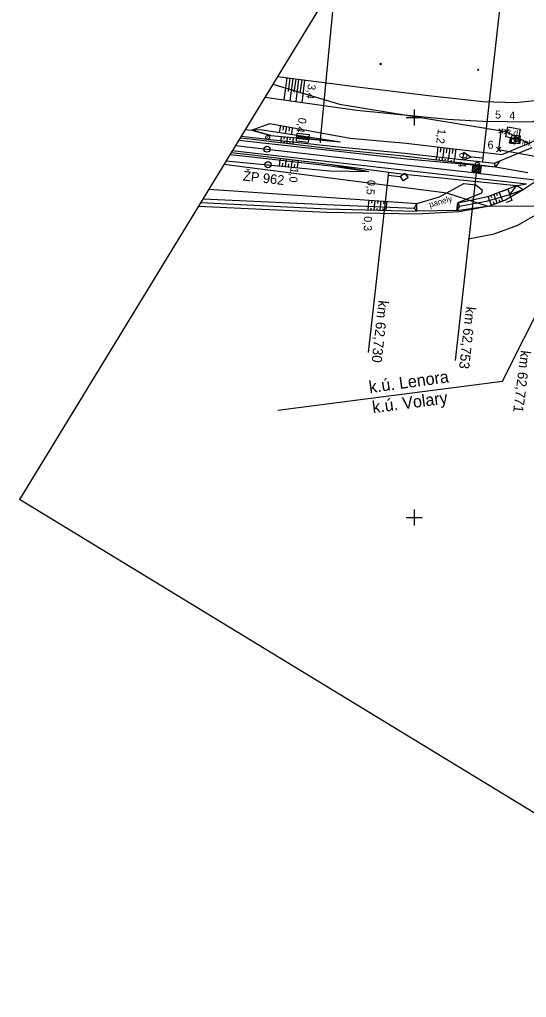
# Model space of a CAD drawing. Extents: x -804899 to -803847, y -1165742 to -1164942.
# Drawn here: x -804898.6 to -804772, y -1165320 to -1165075.5 of the extents above; entities that cross this region are included whole.
import ezdxf

# ---------------------------------------------------------------- set-up
doc = ezdxf.new("R2010")
doc.units = 0
for name, color, linetype in [('0381KM061-064P - Vrstva 1', 7, 'Continuous'), ('0381KM061-064P - Vrstva 16', 7, 'Continuous'), ('0381KM061-064P - Vrstva 23', 7, 'Continuous'), ('0381KM061-064P - Vrstva 27', 7, 'Continuous'), ('0381KM061-064P - Vrstva 3', 7, 'Continuous'), ('0381KM061-064P - Vrstva 33', 7, 'Continuous'), ('0381KM061-064P - Vrstva 4', 7, 'Continuous'), ('0381KM061-064P - Vrstva 43', 7, 'Continuous'), ('0381KM061-064P - Vrstva 48', 7, 'Continuous'), ('0381KM061-064P - Vrstva 49', 7, 'Continuous'), ('0381KM061-064P - Vrstva 51', 7, 'Continuous'), ('0381KM061-064P - Vrstva 55', 7, 'Continuous'), ('0381KM061-064P - Vrstva 7', 7, 'Continuous'), ('0381KM061-064P - Vrstva 8', 7, 'Continuous'), ('Default', 7, 'Continuous'), ('formát', 7, 'Continuous'), ('hran DP - hran DP', 7, 'Continuous'), ('krizky_1000 - Vrstva 1', 7, 'Continuous'), ('PSR_C2_3_Lomove_body_Lenora - Vrstva 60', 7, 'Continuous'), ('PSR_C2_3_trasa_Lenora - Kabelová trasa', 7, 'Continuous'), ('vyt_sit - stávající', 7, 'Continuous')]:
    doc.layers.add(name, color=color, linetype=linetype)

msp = doc.modelspace()

# ---------------------------------------------------------------- linework, layer by layer
at = {"layer": '0381KM061-064P - Vrstva 1'}
for points in [[(-804844.65, -1165107.07), (-804836.78, -1165107.96), (-804807.43, -1165111.28), (-804784.52, -1165113.87), (-804783.45, -1165113.99)], [(-804783.45, -1165113.99), (-804769.78, -1165115.58), (-804758.24, -1165117.11), (-804750.67, -1165118.27), (-804748.02, -1165118.72)]]:
    msp.add_lwpolyline(points, dxfattribs=at)
at = {"layer": '0381KM061-064P - Vrstva 16'}
for p, q in [((-804776.21, -1165106.34), (-804776.22, -1165106.34)), ((-804775.98, -1165105.22), (-804775.98, -1165105.22)), ((-804774.64, -1165105.59), (-804774.63, -1165105.59))]:
    msp.add_line(p, q, dxfattribs=at)
for points in [[(-804774.8, -1165106.64), (-804776.22, -1165106.34), (-804775.98, -1165105.22), (-804774.63, -1165105.59), (-804774.8, -1165106.64)], [(-804774.81, -1165106.64), (-804774.64, -1165105.59), (-804775.98, -1165105.22), (-804776.21, -1165106.34), (-804774.81, -1165106.64), (-804774.8, -1165106.64)], [(-804799.35, -1165123.41), (-804799.3, -1165121.51), (-804793.65, -1165119.83), (-804787.56, -1165116.52), (-804784.63, -1165116.88), (-804783.05, -1165118.1), (-804783.21, -1165118.97), (-804789.08, -1165121.4), (-804789.37, -1165123.31), (-804799.35, -1165123.41)]]:
    msp.add_lwpolyline(points, dxfattribs=at)
at = {"layer": '0381KM061-064P - Vrstva 23'}
msp.add_lwpolyline([(-804776.62, -1165102.34), (-804773.5, -1165102.91), (-804774.04, -1165105.5), (-804777.07, -1165104.85), (-804776.62, -1165102.34)], dxfattribs=at)
at = {"layer": '0381KM061-064P - Vrstva 27'}
for p, q in [((-804774.53, -1165105.54), (-804774.43, -1165105.56)), ((-804784.28, -1165111.73), (-804784.18, -1165111.73))]:
    msp.add_line(p, q, dxfattribs=at)
for centre in [(-804774.48, -1165105.55), (-804784.23, -1165111.73)]:
    msp.add_circle(centre, 0.5, dxfattribs=at)
at = {"layer": '0381KM061-064P - Vrstva 3'}
for p, q in [((-804784.52, -1165113.87), (-804789.79, -1165160.75)), ((-804783.3, -1165111.99), (-804785.51, -1165113.76)), ((-804783.83, -1165111.94), (-804785.45, -1165113.23)), ((-804784.36, -1165111.88), (-804785.4, -1165112.7)), ((-804784.88, -1165111.82), (-804785.34, -1165112.18)), ((-804783.36, -1165112.52), (-804784.99, -1165113.82)), ((-804783.42, -1165113.05), (-804784.46, -1165113.88)), ((-804783.48, -1165113.58), (-804783.93, -1165113.94))]:
    msp.add_line(p, q, dxfattribs=at)
msp.add_lwpolyline([(-804783.53, -1165113.98), (-804785.51, -1165113.76), (-804785.29, -1165111.77), (-804783.3, -1165111.99)], close=True, dxfattribs=at)
at = {"layer": '0381KM061-064P - Vrstva 33'}
for p, q in [((-804775.08, -1165104.96), (-804774.09, -1165105.07)), ((-804774.58, -1165105.01), (-804774.7, -1165106.01))]:
    msp.add_line(p, q, dxfattribs=at)
msp.add_lwpolyline([(-804775.52, -1165104.4), (-804773.53, -1165104.63), (-804773.76, -1165106.62), (-804775.75, -1165106.39), (-804775.52, -1165104.4)], dxfattribs=at)
at = {"layer": '0381KM061-064P - Vrstva 4'}
for points in [[(-804843.83, -1165105.73), (-804840.8, -1165106.06), (-804819.65, -1165108.38), (-804802.7, -1165110.3), (-804779.71, -1165112.39), (-804771.59, -1165113.78)], [(-804843.45, -1165105.1), (-804840.34, -1165105.46), (-804819.52, -1165107.92), (-804802.69, -1165109.64), (-804779.71, -1165112.39)], [(-804845.7, -1165108.79), (-804841.9, -1165109.22), (-804820.58, -1165111.74), (-804803.21, -1165114.08), (-804774.36, -1165117.01), (-804771.98, -1165116.64)], [(-804845.41, -1165108.32), (-804841.86, -1165108.69), (-804820.53, -1165111.13), (-804802.92, -1165113.13), (-804771.98, -1165116.64)]]:
    msp.add_lwpolyline(points, dxfattribs=at)
at = {"layer": '0381KM061-064P - Vrstva 43'}
msp.add_lwpolyline([(-804778.05, -1165118.46), (-804776.64, -1165117.94), (-804775.59, -1165120.75), (-804777, -1165121.27)], dxfattribs=at)
at = {"layer": '0381KM061-064P - Vrstva 48'}
for p, q in [((-804832.45, -1165095.65), (-804831.74, -1165090.13)), ((-804831.42, -1165093.54), (-804831, -1165090.23)), ((-804830.97, -1165095.86), (-804830.25, -1165090.32)), ((-804829.94, -1165093.74), (-804829.51, -1165090.42)), ((-804829.48, -1165096.06), (-804828.77, -1165090.52)), ((-804828.45, -1165093.95), (-804828.02, -1165090.61)), ((-804827.99, -1165096.27), (-804827.28, -1165090.71)), ((-804833.61, -1165103.81), (-804833.29, -1165102.02)), ((-804832.74, -1165103.22), (-804832.55, -1165102.15)), ((-804832.13, -1165104.04), (-804831.81, -1165102.29)), ((-804831.26, -1165103.46), (-804831.07, -1165102.42)), ((-804830.65, -1165104.27), (-804830.33, -1165102.56)), ((-804833.23, -1165105.8), (-804833.29, -1165106.29)), ((-804833.24, -1165105.79), (-804833.15, -1165104.77)), ((-804832.51, -1165106.08), (-804832.54, -1165106.38)), ((-804832.46, -1165105.46), (-804832.4, -1165104.84)), ((-804831.74, -1165105.96), (-804831.8, -1165106.47)), ((-804831.75, -1165105.96), (-804831.66, -1165104.91)), ((-804831.02, -1165106.25), (-804831.05, -1165106.55)), ((-804830.97, -1165105.61), (-804830.91, -1165104.98)), ((-804830.25, -1165106.12), (-804830.31, -1165106.64)), ((-804830.26, -1165106.12), (-804830.16, -1165105.05)), ((-804794.08, -1165107.35), (-804794.37, -1165109.84)), ((-804793.33, -1165107.44), (-804793.48, -1165108.68)), ((-804792.59, -1165107.53), (-804792.88, -1165110.01)), ((-804791.84, -1165107.62), (-804791.99, -1165108.86)), ((-804791.1, -1165107.71), (-804791.39, -1165110.18)), ((-804790.35, -1165107.79), (-804790.5, -1165109.03)), ((-804789.61, -1165107.88), (-804789.9, -1165110.35)), ((-804833.61, -1165112.12), (-804833.46, -1165110.65)), ((-804833.4, -1165110.23), (-804833.45, -1165110.65)), ((-804832.86, -1165112.2), (-804832.79, -1165111.47)), ((-804832.66, -1165110.31), (-804832.68, -1165110.53)), ((-804832.11, -1165112.27), (-804831.97, -1165110.82)), ((-804831.91, -1165110.4), (-804831.96, -1165110.82)), ((-804831.17, -1165110.49), (-804831.19, -1165110.7)), ((-804830.62, -1165112.41), (-804830.48, -1165111)), ((-804830.42, -1165110.58), (-804830.47, -1165111)), ((-804829.68, -1165110.67), (-804829.7, -1165110.87)), ((-804829.13, -1165112.56), (-804828.99, -1165111.17)), ((-804828.93, -1165110.75), (-804828.98, -1165111.17)), ((-804794.47, -1165110.62), (-804794.37, -1165109.84)), ((-804793.72, -1165110.71), (-804793.67, -1165110.32)), ((-804792.98, -1165110.8), (-804792.88, -1165110.01)), ((-804792.23, -1165110.89), (-804792.18, -1165110.49)), ((-804791.49, -1165110.98), (-804791.39, -1165110.18)), ((-804790.74, -1165111.07), (-804790.69, -1165110.67)), ((-804790, -1165111.16), (-804789.9, -1165110.35)), ((-804831.37, -1165112.34), (-804831.3, -1165111.62)), ((-804829.87, -1165112.48), (-804829.81, -1165111.78)), ((-804779.17, -1165119.64), (-804779.44, -1165118.91)), ((-804778.26, -1165119.92), (-804778.74, -1165118.65)), ((-804811.36, -1165120.67), (-804811.46, -1165122.21)), ((-804810.61, -1165120.72), (-804810.66, -1165121.48)), ((-804809.86, -1165120.78), (-804809.96, -1165122.27)), ((-804809.11, -1165120.83), (-804809.16, -1165121.56)), ((-804808.36, -1165120.88), (-804808.46, -1165122.33)), ((-804807.62, -1165120.93), (-804807.67, -1165121.65)), ((-804806.87, -1165120.98), (-804806.97, -1165122.39)), ((-804781.15, -1165120.77), (-804781.55, -1165119.71)), ((-804781.16, -1165120.78), (-804780.73, -1165121.92)), ((-804780.59, -1165120.11), (-804780.84, -1165119.44)), ((-804780.27, -1165121), (-804780.03, -1165121.66)), ((-804779.71, -1165120.34), (-804780.14, -1165119.18)), ((-804779.71, -1165120.35), (-804779.33, -1165121.4)), ((-804778.85, -1165120.54), (-804778.62, -1165121.14)), ((-804778.28, -1165119.92), (-804777.92, -1165120.88)), ((-804811.47, -1165123.14), (-804811.45, -1165122.21)), ((-804810.72, -1165123.15), (-804810.71, -1165122.7)), ((-804809.97, -1165123.17), (-804809.95, -1165122.27)), ((-804809.22, -1165123.19), (-804809.21, -1165122.74)), ((-804808.47, -1165123.2), (-804808.45, -1165122.33)), ((-804807.72, -1165123.22), (-804807.71, -1165122.79)), ((-804806.97, -1165123.24), (-804806.95, -1165122.39))]:
    msp.add_line(p, q, dxfattribs=at)
at = {"layer": '0381KM061-064P - Vrstva 49'}
for p, q in [((-804808.18, -1165086.83), (-804808.54, -1165086.48)), ((-804808.18, -1165086.48), (-804808.54, -1165086.83)), ((-804783.82, -1165088.3), (-804784.18, -1165087.95)), ((-804783.82, -1165087.95), (-804784.18, -1165088.3))]:
    msp.add_line(p, q, dxfattribs=at)
for points in [[(-804782.93, -1165100.95), (-804770.45, -1165101.13), (-804760.77, -1165096.17), (-804750.38, -1165086.38), (-804747.77, -1165080.29)], [(-804834.14, -1165089.82), (-804812.85, -1165092.56), (-804796.39, -1165094.52), (-804782.73, -1165096.03), (-804774.67, -1165096.28), (-804769.92, -1165095.77)], [(-804837.28, -1165094.97), (-804814.35, -1165098.18)], [(-804778.12, -1165109.25), (-804771.87, -1165106.67), (-804764.3, -1165103.24), (-804757.01, -1165099.37), (-804754.14, -1165096.35)], [(-804814.35, -1165098.18), (-804791.62, -1165100.43), (-804782.93, -1165100.95)], [(-804840.64, -1165103.22), (-804836.05, -1165101.51), (-804816.03, -1165105.18), (-804802.02, -1165106.41), (-804778.12, -1165109.25)], [(-804842.2, -1165103.05), (-804840.64, -1165103.22)], [(-804840.64, -1165103.22), (-804838.47, -1165103.07), (-804818.4, -1165106.14)], [(-804840.64, -1165103.22), (-804835.82, -1165104.53), (-804840.64, -1165103.22), (-804835.82, -1165104.53), (-804818.4, -1165106.14)], [(-804843.45, -1165105.1), (-804840.34, -1165105.46), (-804819.52, -1165107.92), (-804802.69, -1165109.64), (-804779.71, -1165112.39)], [(-804843.18, -1165104.66), (-804835.93, -1165105.5), (-804818.93, -1165107.36), (-804802.32, -1165108.93), (-804779.97, -1165111.49)], [(-804845.7, -1165108.79), (-804841.9, -1165109.22), (-804820.58, -1165111.74), (-804811.31, -1165113.56)], [(-804778.59, -1165110.84), (-804770.54, -1165107.5)], [(-804846.95, -1165110.84), (-804821.13, -1165113.33), (-804811.31, -1165113.56)], [(-804845.98, -1165109.25), (-804842.05, -1165109.66), (-804820.85, -1165112.11), (-804811.31, -1165113.56)], [(-804779.71, -1165112.39), (-804779.97, -1165111.49), (-804778.59, -1165110.84)], [(-804778.59, -1165110.84), (-804779.71, -1165112.39)], [(-804851.29, -1165117.97), (-804821.94, -1165119.94), (-804799.3, -1165121.51)], [(-804789.08, -1165121.4), (-804781.63, -1165119.74), (-804774.36, -1165117.01)], [(-804781.18, -1165122.08), (-804777.38, -1165120.68), (-804772.77, -1165118.03)], [(-804776.1, -1165119.27), (-804774.36, -1165117.01)], [(-804776.1, -1165119.27), (-804772.77, -1165118.03)], [(-804774.36, -1165117.01), (-804772.77, -1165118.03)], [(-804853.31, -1165121.27), (-804821.85, -1165122.9), (-804799.35, -1165123.41)], [(-804852.74, -1165120.35), (-804821.99, -1165121.8), (-804800.02, -1165122.66)], [(-804788.67, -1165122.22), (-804781.58, -1165120.9), (-804776.1, -1165119.27)], [(-804799.3, -1165121.51), (-804800.02, -1165122.66), (-804799.35, -1165123.41)], [(-804789.37, -1165123.31), (-804789.08, -1165121.4)], [(-804789.08, -1165121.4), (-804788.67, -1165122.22), (-804789.37, -1165123.31)], [(-804789.37, -1165123.31), (-804781.18, -1165122.08)]]:
    msp.add_lwpolyline(points, dxfattribs=at)
at = {"layer": '0381KM061-064P - Vrstva 51'}
for points in [[(-804799.4, -1165124.13), (-804788.79, -1165123.56), (-804781.18, -1165122.08), (-804777.38, -1165120.68), (-804772.77, -1165118.03), (-804766.25, -1165113.72), (-804759.19, -1165108.08), (-804752.39, -1165104.15), (-804745.74, -1165101.09), (-804737.37, -1165099.16), (-804728.56, -1165098.53)], [(-804786.51, -1165130.38), (-804780.05, -1165129.08), (-804774.13, -1165126.91), (-804767.62, -1165123.23), (-804757.45, -1165115.32), (-804754.9, -1165113.7), (-804749.49, -1165110.74), (-804743.99, -1165108.46), (-804736.29, -1165106.6), (-804728.9, -1165105.9)], [(-804853.87, -1165122.19), (-804821.92, -1165123.67), (-804799.4, -1165124.13)]]:
    msp.add_lwpolyline(points, dxfattribs=at)
at = {"layer": '0381KM061-064P - Vrstva 55'}
msp.add_lwpolyline([(-804834.02, -1165173.21), (-804777.95, -1165165.95), (-804761.65, -1165133.49), (-804755.48, -1165121.19), (-804751.26, -1165114.04), (-804741.92, -1165100.8), (-804736.13, -1165096.49), (-804701.79, -1165069.72), (-804628.3, -1165012.44)], dxfattribs=at)
at = {"layer": '0381KM061-064P - Vrstva 7'}
msp.add_line((-804836.67, -1165105.01), (-804836.57, -1165105.03), dxfattribs=at)
for centre, radius in [((-804836.62, -1165105.02), 0.5), ((-804836.78, -1165107.96), 0.75)]:
    msp.add_circle(centre, radius, dxfattribs=at)
at = {"layer": '0381KM061-064P - Vrstva 8'}
for p, q in [((-804782.75, -1165110.24), (-804774.89, -1165040.2)), ((-804823.36, -1165105.59), (-804819.58, -1165065.95)), ((-804829.06, -1165104.6), (-804829.31, -1165104.79)), ((-804828.53, -1165104.66), (-804829.3, -1165105.27)), ((-804828.01, -1165104.72), (-804828.78, -1165105.33)), ((-804827.48, -1165104.77), (-804828.25, -1165105.39)), ((-804826.95, -1165104.83), (-804827.72, -1165105.45)), ((-804826.42, -1165104.89), (-804827.2, -1165105.51)), ((-804826.35, -1165105.31), (-804826.67, -1165105.57)), ((-804823.44, -1165106.34), (-804823.28, -1165104.85)), ((-804787.62, -1165108.74), (-804785.73, -1165109.94)), ((-804782.82, -1165110.99), (-804782.67, -1165109.49)), ((-804806.43, -1165113.71), (-804806.59, -1165115.21)), ((-804806.51, -1165114.46), (-804811.49, -1165158.76))]:
    msp.add_line(p, q, dxfattribs=at)
for points in [[(-804826.45, -1165106.25), (-804829.43, -1165105.91), (-804829.21, -1165103.92), (-804826.23, -1165104.26), (-804826.45, -1165106.25)], [(-804826.34, -1165105.26), (-804823.36, -1165105.59)], [(-804782.75, -1165110.24), (-804785.73, -1165109.94), (-804787.82, -1165110.73), (-804787.62, -1165108.74), (-804785.73, -1165109.94)], [(-804806.51, -1165114.46), (-804803.53, -1165114.8), (-804802.42, -1165113.91), (-804801.54, -1165115.02), (-804802.65, -1165115.9), (-804803.53, -1165114.8)]]:
    msp.add_lwpolyline(points, dxfattribs=at)
msp.add_lwpolyline([(-804826.38, -1165105.6), (-804829.36, -1165105.26), (-804829.28, -1165104.57), (-804826.3, -1165104.91)], close=True, dxfattribs=at)
at = {"layer": 'formát'}
for p in [(-804743.98, -1164941.92), (-804360.64, -1165523.44)]:
    msp.add_line(p, (-804898.57, -1165195.52), dxfattribs=at)
at = {"layer": 'hran DP - hran DP'}
for p, q in [((-804835.27, -1165091.67), (-804818.68, -1165096.66)), ((-804818.68, -1165096.66), (-804777.08, -1165103.56)), ((-804777.08, -1165103.56), (-804771.09, -1165106.6)), ((-804791.88, -1165118.97), (-804847.53, -1165111.8)), ((-804781.51, -1165122.32), (-804791.88, -1165118.97)), ((-804765.27, -1165122.22), (-804781.51, -1165122.32))]:
    msp.add_line(p, q, dxfattribs=at)
at = {"layer": 'krizky_1000 - Vrstva 1'}
for points in [[(-804800, -1165098), (-804800, -1165102)], [(-804802, -1165100), (-804798, -1165100)], [(-804800, -1165198), (-804800, -1165202)], [(-804802, -1165200), (-804798, -1165200)]]:
    msp.add_lwpolyline(points, dxfattribs=at)
at = {"layer": 'PSR_C2_3_Lomove_body_Lenora - Vrstva 60'}
for p, q in [((-804778.89, -1165103.96), (-804777.79, -1165102.86)), ((-804777.79, -1165103.96), (-804778.89, -1165102.86)), ((-804777.4, -1165104.14), (-804776.3, -1165103.04)), ((-804776.3, -1165104.14), (-804777.4, -1165103.04)), ((-804779.47, -1165108.59), (-804778.37, -1165107.49)), ((-804778.37, -1165108.59), (-804779.47, -1165107.49))]:
    msp.add_line(p, q, dxfattribs=at)
at = {"layer": 'PSR_C2_3_trasa_Lenora - Kabelová trasa'}
msp.add_lwpolyline([(-804776.85, -1165103.59), (-804778.34, -1165103.41), (-804778.92, -1165108.04), (-804764.44, -1165110.74), (-804751.18, -1165114.27), (-804752.83, -1165121.07), (-804765.02, -1165122.88)], dxfattribs=at)
at = {"layer": 'vyt_sit - stávající'}
msp.add_line((-804836.57, -1165111.8), (-804836.48, -1165111.85), dxfattribs=at)
msp.add_circle((-804836.52, -1165111.83), 0.756, dxfattribs=at)

# ---------------------------------------------------------------- texts
at = {"layer": '0381KM061-064P - Vrstva 16'}
for s, rotation, p in [('panel.', 348.0707, (-804776, -1165106.18)), ('panely', 16.5596, (-804796.03, -1165122.6))]:
    msp.add_text(s, height=1.5, rotation=rotation, dxfattribs=at).set_placement(p)
at = {"layer": '0381KM061-064P - Vrstva 23'}
msp.add_text('r.d.', height=1.5, rotation=349.7146, dxfattribs=at).set_placement((-804776.52, -1165104.36))
at = {"layer": '0381KM061-064P - Vrstva 3'}
msp.add_text('km 62,753', height=2.5, rotation=263.5832, dxfattribs=at).set_placement((-804787.04, -1165147.22))
at = {"layer": '0381KM061-064P - Vrstva 4'}
msp.add_text('km 62,771', height=2.5, rotation=262.8793, dxfattribs=at).set_placement((-804773.35, -1165158.16))
at = {"layer": '0381KM061-064P - Vrstva 48'}
for s, rotation, p in [('3,4', 262.6656, (-804826.51, -1165091.58)), ('0,4', 259.6289, (-804828.81, -1165099.95)), ('1,2', 263.2123, (-804794.05, -1165102.78)), ('0,4', 263.1664, (-804788.64, -1165108.7)), ('1,0', 264.4873, (-804830.87, -1165112.47)), ('0,5', 266.024, (-804811.67, -1165115.58)), ('0,3', 268.6994, (-804812.52, -1165124.7))]:
    msp.add_text(s, height=2, rotation=rotation, dxfattribs=at).set_placement(p)
at = {"layer": '0381KM061-064P - Vrstva 55'}
for s, rotation, p in [('k.ú. Lenora', 7.7713, (-804811.1, -1165168.94)), ('k.ú. Volary', 7.4655, (-804810.29, -1165173.96))]:
    msp.add_text(s, height=3, rotation=rotation, dxfattribs=at).set_placement(p)
at = {"layer": '0381KM061-064P - Vrstva 8'}
msp.add_text('km 62,730', height=2.5, rotation=263.5832, dxfattribs=at).set_placement((-804808.89, -1165145.66))
at = {"layer": 'Default'}
for s, p in [('5', (-804779.79, -1165100.31)), ('4', (-804776.23, -1165100.55)), ('6', (-804781.67, -1165107.84))]:
    msp.add_text(s, height=2, dxfattribs=at).set_placement(p)
at = {"layer": 'vyt_sit - stávající'}
msp.add_text('ŽP 962', height=2.4, rotation=353.5611, dxfattribs=at).set_placement((-804842.86, -1165115.77))

doc.saveas('drawing.dxf')
